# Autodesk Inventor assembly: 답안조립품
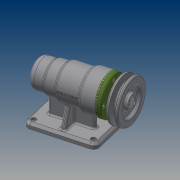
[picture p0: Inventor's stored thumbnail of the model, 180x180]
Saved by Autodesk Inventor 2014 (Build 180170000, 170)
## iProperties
Created: 2016-06
Part Number: 답안조립품
Document SubType Name: Assembly
Designer: SEC
Author: SEC
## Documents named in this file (11)
- C:\Documents and Settings\SEC\바탕 화면\460607V1005\답안조립품.iam
- C:\Documents and Settings\SEC\바탕 화면\460607V1005\1-본체.ipt
- C:\Documents and Settings\SEC\바탕 화면\460607V1005\커버.ipt
- C:\Documents and Settings\SEC\바탕 화면\460607V1005\베어링 6004.ipt
- C:\Documents and Settings\SEC\바탕 화면\460607V1005\축.ipt
- C:\Documents and Settings\SEC\바탕 화면\460607V1005\어댑터슬리브.ipt
- C:\Documents and Settings\SEC\바탕 화면\460607V1005\볼트 M4 x 12.ipt
- C:\Documents and Settings\SEC\바탕 화면\460607V1005\베어링 51202.ipt
- C:\Documents and Settings\SEC\바탕 화면\460607V1005\키 5 x 5 x 16.ipt
- C:\Documents and Settings\SEC\바탕 화면\460607V1005\V벨트풀리.ipt
- C:\Documents and Settings\SEC\바탕 화면\460607V1005\멈춤나사 M3x8.ipt
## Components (7 placed, 3 different names)
1. ISO 4762 M4 x 12:1
2. 1-본체:1
3. V벨트풀리:1 — 각도:2
4. ISO 4762 M4 x 12:2
5. ISO 4762 M4 x 12:3
6. ISO 4762 M4 x 12:4
7. ISO 4762 M4 x 12:5
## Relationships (1: Angle 1)
- 각도:2 [Angle]: V벨트풀리:1
